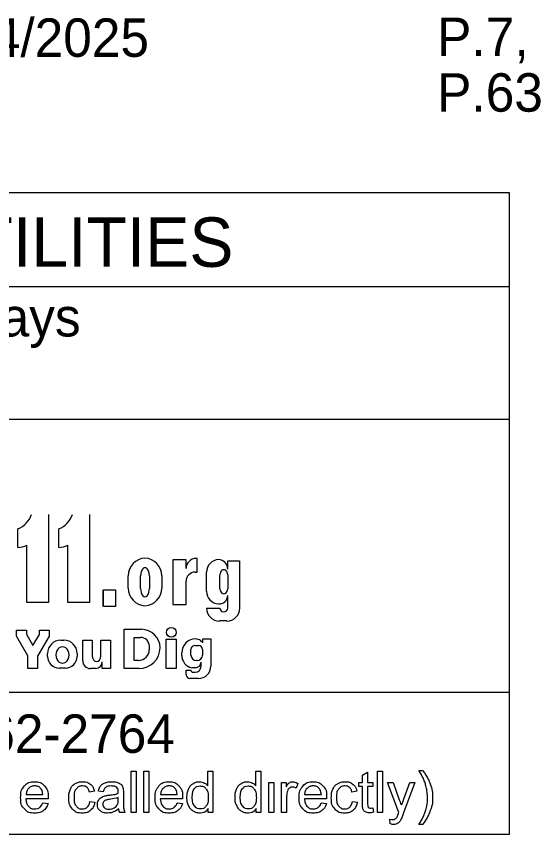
# Model space of a CAD drawing. Extents: x 0 to 34, y -32.5 to 22.
# Drawn here: x 4.831 to 6.74, y 2.305 to 5.285 of the extents above; entities that cross this region are included whole.
import ezdxf

# ---------------------------------------------------------------- set-up
doc = ezdxf.new("R2010")
doc.units = 0
doc.layers.add('GM_X_Adjacent_County', color=7, linetype='Continuous')
doc.layers.add('GM_X_Township', color=7, linetype='Continuous')

msp = doc.modelspace()

# ---------------------------------------------------------------- linework, layer by layer
at = {"layer": 'GM_X_Adjacent_County'}
for p, q in [((4.9487, 3.4706), (4.9487, 3.1506)), ((5.0975, 3.4706), (5.0975, 3.1506)), ((4.8371, 3.3499), (4.8371, 3.418)), ((4.9859, 3.3499), (4.9859, 3.418)), ((4.8694, 3.1506), (4.8694, 3.3592)), ((5.0182, 3.1506), (5.0182, 3.3592)), ((5.49, 3.3106), (5.486, 3.3106)), ((5.49, 3.2607), (5.49, 3.3106)), ((5.4493, 3.3054), (5.4005, 3.3054)), ((5.4005, 3.3054), (5.4005, 3.1425)), ((5.4493, 3.2739), (5.4493, 3.3054)), ((5.6009, 3.2713), (5.6009, 3.3023)), ((5.6009, 3.3023), (5.6444, 3.3023)), ((5.6444, 3.3023), (5.6444, 3.1294)), ((5.4823, 3.2607), (5.49, 3.2607)), ((5.5239, 3.1908), (5.5239, 3.2605)), ((5.5723, 3.2002), (5.5723, 3.2512)), ((5.6009, 3.2512), (5.6009, 3.2002)), ((5.2385, 3.2023), (5.2385, 3.2477)), ((5.2835, 3.2015), (5.2835, 3.2477)), ((5.3157, 3.2477), (5.3157, 3.2015)), ((5.3606, 3.2477), (5.3606, 3.2023)), ((5.4493, 3.1425), (5.4493, 3.2277)), ((5.1456, 3.1956), (5.1456, 3.1355)), ((5.6009, 3.1294), (5.6009, 3.1758)), ((4.9487, 3.1506), (4.8694, 3.1506)), ((5.0975, 3.1506), (5.0182, 3.1506)), ((5.4005, 3.1425), (5.4493, 3.1425)), ((5.5239, 3.1294), (5.5723, 3.1294)), ((5.5977, 3.0827), (5.5707, 3.0827)), ((4.8319, 3.0489), (4.8677, 3.0489)), ((4.8319, 3.0274), (4.8319, 3.0489)), ((4.8677, 3.0489), (4.8677, 3.0353)), ((4.9151, 3.0337), (4.9151, 3.0489)), ((4.9151, 3.0489), (4.9509, 3.0489)), ((4.9509, 3.0489), (4.9509, 3.0274)), ((5.2243, 3.0525), (5.2866, 3.0525)), ((5.2243, 2.9097), (5.2243, 3.0525)), ((4.8732, 2.9564), (4.8319, 3.0274)), ((4.8677, 3.0353), (4.8918, 2.9939)), ((4.8918, 2.9939), (4.9151, 3.0337)), ((4.9509, 3.0274), (4.9088, 2.955)), ((4.9925, 3.0126), (5.0047, 3.0126)), ((5.0727, 3.0126), (5.1075, 3.0126)), ((5.0727, 2.9381), (5.0727, 3.0126)), ((5.1075, 3.0126), (5.1075, 2.9573)), ((5.1388, 2.9556), (5.1388, 3.0126)), ((5.1388, 3.0126), (5.1736, 3.0126)), ((5.1736, 3.0126), (5.1736, 2.9097)), ((5.2603, 2.9391), (5.2603, 3.0232)), ((5.2603, 3.0232), (5.2828, 3.0232)), ((5.377, 3.0168), (5.4126, 3.0168)), ((5.377, 2.9097), (5.377, 3.0168)), ((5.4126, 3.0168), (5.4126, 2.9097)), ((5.5021, 3.0112), (5.5107, 3.0046)), ((5.5107, 3.0172), (5.5395, 3.0172)), ((5.5107, 3.0046), (5.5107, 3.0172)), ((5.5107, 3.0172), (5.5395, 3.0172)), ((5.5395, 3.0172), (5.5395, 2.9186)), ((5.3154, 2.9905), (5.3154, 2.9786)), ((5.4816, 2.9938), (5.4944, 2.9938)), ((4.8732, 2.9097), (4.8732, 2.9564)), ((4.9088, 2.955), (4.9088, 2.9097)), ((4.9447, 2.954), (4.9447, 2.9648)), ((5.0525, 2.9648), (5.0525, 2.954)), ((5.4335, 2.9572), (5.4335, 2.9673)), ((5.467, 2.958), (5.467, 2.9792)), ((5.509, 2.9792), (5.509, 2.958)), ((5.1439, 2.9097), (5.1439, 2.9338)), ((5.2759, 2.9391), (5.2603, 2.9391)), ((5.4897, 2.9387), (5.4863, 2.9387)), ((5.5039, 2.9176), (5.5039, 2.933)), ((4.9088, 2.9097), (4.8732, 2.9097)), ((5.0097, 2.9113), (4.9875, 2.9113)), ((5.1199, 2.9097), (5.1011, 2.9097)), ((5.1736, 2.9097), (5.1439, 2.9097)), ((5.2779, 2.9097), (5.2243, 2.9097)), ((5.4126, 2.9097), (5.377, 2.9097)), ((5.45, 2.8864), (5.45, 2.9034)), ((5.45, 2.9034), (5.467, 2.9034)), ((5.4835, 2.9125), (5.4698, 2.9125)), ((5.4738, 2.8964), (5.4827, 2.8964)), ((5.4942, 2.8733), (5.4631, 2.8733))]:
    msp.add_line(p, q, dxfattribs=at)
msp.add_lwpolyline([(5.148, 3.1956), (5.1921, 3.1956), (5.1921, 3.1355), (5.148, 3.1355)], close=True, dxfattribs=at)
for points in [[(5.2491, 2.3858), (5.2491, 2.536), (5.2675, 2.536), (5.2675, 2.3858), (5.2491, 2.3858)], [(5.2956, 2.3858), (5.2956, 2.536), (5.3141, 2.536), (5.3141, 2.3858), (5.2956, 2.3858)], [(5.5285, 2.4821), (5.5285, 2.536), (5.5469, 2.536), (5.5469, 2.3858), (5.5299, 2.3858)], [(5.7034, 2.4821), (5.7034, 2.536), (5.7218, 2.536), (5.7218, 2.3858), (5.7048, 2.3858)], [(6.1465, 2.3858), (6.1465, 2.536), (6.1649, 2.536), (6.1649, 2.3858), (6.1465, 2.3858)], [(6.2974, 2.5385), (6.3105, 2.5385)], [(6.092, 2.4177), (6.092, 2.4803), (6.0784, 2.4803), (6.0784, 2.4946), (6.092, 2.4946), (6.092, 2.5216), (6.1105, 2.5326), (6.1105, 2.4946), (6.1289, 2.4946), (6.1289, 2.4803), (6.1105, 2.4803), (6.1105, 2.4166)], [(5.7509, 2.3858), (5.7509, 2.4946), (5.7693, 2.4946), (5.7693, 2.3858), (5.7509, 2.3858)], [(5.7971, 2.3858), (5.7971, 2.4946), (5.8137, 2.4946), (5.8137, 2.4782)], [(5.8562, 2.4912), (5.8497, 2.4741)], [(6.2243, 2.3857), (6.183, 2.4946), (6.2029, 2.4946), (6.2255, 2.4318)], [(6.241, 2.4312), (6.2643, 2.4946), (6.2827, 2.4946), (6.2414, 2.3839)], [(4.8669, 2.4506), (4.9277, 2.4506)], [(5.1154, 2.4626), (5.0974, 2.4599)], [(5.1479, 2.4611), (5.1298, 2.4635)], [(5.2209, 2.456), (5.2209, 2.4314)], [(5.3565, 2.4506), (5.4173, 2.4506)], [(5.881, 2.4506), (5.9418, 2.4506)], [(6.0712, 2.4626), (6.0532, 2.4599)], [(4.947, 2.4355), (4.8659, 2.4355)], [(4.9275, 2.4209), (4.9465, 2.4185)], [(5.099, 2.4256), (5.1171, 2.4232)], [(5.2023, 2.4336), (5.2024, 2.4404)], [(5.4366, 2.4355), (5.3555, 2.4355)], [(5.4171, 2.4209), (5.4361, 2.4185)], [(5.8155, 2.4428), (5.8155, 2.3858), (5.7971, 2.3858)], [(5.9611, 2.4355), (5.88, 2.4355)], [(5.9416, 2.4209), (5.9606, 2.4185)], [(6.0548, 2.4256), (6.0729, 2.4232)], [(5.2267, 2.3858), (5.2075, 2.3858)], [(5.5299, 2.3858), (5.5299, 2.3995)], [(5.7048, 2.3858), (5.7048, 2.3995)], [(6.1289, 2.4022), (6.1315, 2.386)], [(6.1928, 2.344), (6.1907, 2.3614)], [(6.3105, 2.3416), (6.2974, 2.3416)]]:
    msp.add_lwpolyline(points, dxfattribs=at)
msp.add_circle((5.3952, 3.0411), 0.0177, dxfattribs=at)
for centre, radius, start, end in [((4.8031, 3.4997), 0.0885, 292.5572, 340.7355), ((4.952, 3.4997), 0.0885, 292.5572, 340.7355), ((4.8291, 3.438), 0.0885, 275.1733, 297.0931), ((4.9779, 3.438), 0.0885, 275.1733, 297.0931), ((5.3024, 3.2477), 0.064, 92.5886, 180), ((5.2967, 3.2477), 0.064, 0, 87.4114), ((5.486, 3.2739), 0.0367, 90, 180), ((5.5698, 3.2605), 0.0459, 92.6865, 180), ((5.5658, 3.2713), 0.0351, 0, 86.9262), ((5.4823, 3.2277), 0.033, 90, 180), ((5.3024, 3.2023), 0.064, 180, 267.4114), ((5.2967, 3.2023), 0.064, 272.5886, 0), ((5.5702, 3.1908), 0.0463, 180, 265.7132), ((5.5696, 3.1758), 0.0313, 264.7825, 0), ((5.5707, 3.1294), 0.0468, 180, 270), ((5.5977, 3.1294), 0.0468, 270, 0), ((5.2866, 2.9842), 0.0682, 0.9944, 90), ((4.9925, 2.9648), 0.0478, 90, 180), ((5.0047, 2.9648), 0.0478, 0, 90), ((5.2828, 2.9905), 0.0327, 0, 90), ((5.4834, 2.9673), 0.0499, 89.0934, 180), ((5.4848, 2.9889), 0.0283, 52.1415, 91.2046), ((5.2779, 2.9867), 0.0769, 270, 359.0635), ((5.4816, 2.9792), 0.0146, 90, 180), ((5.4944, 2.9792), 0.0146, 0, 90), ((4.9875, 2.954), 0.0428, 180, 270), ((5.0097, 2.954), 0.0428, 270, 0), ((5.2759, 2.9786), 0.0395, 270, 0), ((5.4791, 2.9572), 0.0457, 180, 258.2203), ((5.4863, 2.958), 0.0193, 180, 270), ((5.4897, 2.958), 0.0193, 270, 0), ((5.1011, 2.9381), 0.0284, 180, 270), ((5.1199, 2.9338), 0.024, 270, 0), ((5.4835, 2.9328), 0.0203, 270, 0), ((5.4738, 2.9032), 0.00682, 180, 270), ((5.4827, 2.9176), 0.0212, 270, 0), ((5.4942, 2.9186), 0.0453, 270, 0), ((5.4631, 2.8864), 0.0131, 180, 270)]:
    msp.add_arc(centre, radius, start, end, dxfattribs=at)
for centre, major_axis, ratio, start_param, end_param in [((5.2996, 3.2477), (0, 0.0291), 0.553236, 4.712389, 7.853982), ((5.5866, 3.2512), (0, 0.0184), 0.777179, 4.712389, 7.853982), ((5.2996, 3.2015), (0, 0.0308), 0.522014, 1.570796, 4.712389), ((5.5866, 3.2002), (0, 0.0184), 0.777179, 1.570796, 4.712389), ((5.5866, 3.1294), (0.0143, 0), 0.959012, 3.141593, 6.283185), ((4.9991, 2.9594), (0, 0.029), 0.832186, 4.712389, 7.853982), ((4.9991, 2.9594), (0, 0.0302), 0.797287, 1.570796, 4.712389), ((5.1231, 2.9581), (-0.0011, 0.0231), 0.679042, 1.570796, 4.575961)]:
    msp.add_ellipse(centre, major_axis=major_axis, ratio=ratio, start_param=start_param, end_param=end_param, dxfattribs=at)
for points, degree in [([(6.2974, 2.3416), (6.3279, 2.3908), (6.3279, 2.4401), (6.3279, 2.4593), (6.3235, 2.4783), (6.32, 2.4936), (6.3138, 2.5078), (6.3098, 2.517), (6.2974, 2.5385)], 3), ([(6.3105, 2.5385), (6.3298, 2.5128), (6.339, 2.4869), (6.3469, 2.4645), (6.3469, 2.4402), (6.3469, 2.4125), (6.3363, 2.3867), (6.3257, 2.3609), (6.3105, 2.3416)], 3), ([(4.9465, 2.4185), (4.942, 2.4018), (4.9298, 2.3926), (4.9177, 2.3834), (4.8987, 2.3834), (4.8749, 2.3834), (4.8609, 2.3981), (4.8469, 2.4128), (4.8469, 2.4393), (4.8469, 2.4667), (4.861, 2.4819), (4.8752, 2.497), (4.8977, 2.497), (4.9195, 2.497), (4.9333, 2.4822), (4.9471, 2.4673), (4.9471, 2.4404), (4.9471, 2.4388), (4.947, 2.4355)], 3), ([(4.9277, 2.4506), (4.9265, 2.4644), (4.9207, 2.4712), (4.9119, 2.4819), (4.8979, 2.4819), (4.8852, 2.4819), (4.8765, 2.4734), (4.8678, 2.4649), (4.8669, 2.4506)], 3), ([(5.1171, 2.4232), (5.1141, 2.4045), (5.1019, 2.394), (5.0896, 2.3834), (5.0718, 2.3834), (5.0495, 2.3834), (5.0359, 2.398), (5.0223, 2.4126), (5.0223, 2.4398), (5.0223, 2.4574), (5.0282, 2.4706), (5.034, 2.4838), (5.046, 2.4904), (5.0579, 2.497), (5.0719, 2.497), (5.0897, 2.497), (5.1009, 2.4881), (5.1122, 2.4791), (5.1154, 2.4626)], 3), ([(5.0974, 2.4599), (5.0949, 2.4708), (5.0884, 2.4764), (5.0819, 2.4819), (5.0726, 2.4819), (5.0587, 2.4819), (5.05, 2.4719), (5.0413, 2.462), (5.0413, 2.4403), (5.0413, 2.4184), (5.0497, 2.4085), (5.0581, 2.3985), (5.0717, 2.3985), (5.0825, 2.3985), (5.0898, 2.4052), (5.0971, 2.4118), (5.099, 2.4256)], 3), ([(5.2038, 2.3992), (5.1936, 2.3905), (5.1841, 2.387), (5.1746, 2.3834), (5.1638, 2.3834), (5.1458, 2.3834), (5.1362, 2.3922), (5.1266, 2.4009), (5.1266, 2.4145), (5.1266, 2.4225), (5.1302, 2.4291), (5.1339, 2.4357), (5.1398, 2.4397), (5.1456, 2.4437), (5.153, 2.4457), (5.1584, 2.4471), (5.1694, 2.4485), (5.1917, 2.4511), (5.2023, 2.4548), (5.2024, 2.4586), (5.2024, 2.4596), (5.2024, 2.4709), (5.1971, 2.4756), (5.1901, 2.4818), (5.1762, 2.4818), (5.1632, 2.4818), (5.157, 2.4773), (5.1508, 2.4727), (5.1479, 2.4611)], 3), ([(5.1298, 2.4635), (5.1323, 2.4751), (5.1379, 2.4822), (5.1435, 2.4894), (5.1542, 2.4932), (5.1648, 2.497), (5.1788, 2.497), (5.1928, 2.497), (5.2015, 2.4938), (5.2102, 2.4905), (5.2142, 2.4855), (5.2183, 2.4805), (5.22, 2.473), (5.2209, 2.4682), (5.2209, 2.456)], 3), ([(5.4361, 2.4185), (5.4316, 2.4018), (5.4194, 2.3926), (5.4072, 2.3834), (5.3883, 2.3834), (5.3644, 2.3834), (5.3505, 2.3981), (5.3365, 2.4128), (5.3365, 2.4393), (5.3365, 2.4667), (5.3506, 2.4819), (5.3648, 2.497), (5.3873, 2.497), (5.4091, 2.497), (5.4229, 2.4822), (5.4367, 2.4673), (5.4367, 2.4404), (5.4367, 2.4388), (5.4366, 2.4355)], 3), ([(5.4173, 2.4506), (5.4161, 2.4644), (5.4103, 2.4712), (5.4015, 2.4819), (5.3875, 2.4819), (5.3748, 2.4819), (5.3661, 2.4734), (5.3574, 2.4649), (5.3565, 2.4506)], 3), ([(5.5299, 2.3995), (5.5195, 2.3834), (5.4995, 2.3834), (5.4865, 2.3834), (5.4755, 2.3906), (5.4646, 2.3977), (5.4586, 2.4106), (5.4526, 2.4234), (5.4526, 2.4401), (5.4526, 2.4564), (5.4581, 2.4697), (5.4635, 2.4829), (5.4743, 2.49), (5.4852, 2.497), (5.4986, 2.497), (5.5084, 2.497), (5.516, 2.4929), (5.5237, 2.4888), (5.5285, 2.4821)], 3), ([(5.4716, 2.4401), (5.4716, 2.4192), (5.4805, 2.4089), (5.4893, 2.3985), (5.5012, 2.3985), (5.5133, 2.3985), (5.5218, 2.4084), (5.5302, 2.4183), (5.5302, 2.4386), (5.5302, 2.4609), (5.5216, 2.4714), (5.513, 2.4818), (5.5004, 2.4818), (5.4881, 2.4818), (5.4799, 2.4718), (5.4716, 2.4617), (5.4716, 2.4401)], 3), ([(5.7048, 2.3995), (5.6944, 2.3834), (5.6743, 2.3834), (5.6613, 2.3834), (5.6504, 2.3906), (5.6395, 2.3977), (5.6335, 2.4106), (5.6275, 2.4234), (5.6275, 2.4401), (5.6275, 2.4564), (5.6329, 2.4697), (5.6384, 2.4829), (5.6492, 2.49), (5.66, 2.497), (5.6734, 2.497), (5.6832, 2.497), (5.6909, 2.4929), (5.6986, 2.4888), (5.7034, 2.4821)], 3), ([(5.6465, 2.4401), (5.6465, 2.4192), (5.6553, 2.4089), (5.6641, 2.3985), (5.6761, 2.3985), (5.6882, 2.3985), (5.6967, 2.4084), (5.7051, 2.4183), (5.7051, 2.4386), (5.7051, 2.4609), (5.6965, 2.4714), (5.6879, 2.4818), (5.6753, 2.4818), (5.663, 2.4818), (5.6548, 2.4718), (5.6465, 2.4617), (5.6465, 2.4401)], 3), ([(5.8137, 2.4782), (5.8201, 2.4897), (5.8254, 2.4934), (5.8308, 2.497), (5.8372, 2.497), (5.8466, 2.497), (5.8562, 2.4912)], 3), ([(5.8497, 2.4741), (5.843, 2.478), (5.8363, 2.478), (5.8302, 2.478), (5.8255, 2.4744), (5.8207, 2.4708), (5.8186, 2.4643), (5.8155, 2.4545), (5.8155, 2.4428)], 3), ([(5.9606, 2.4185), (5.9561, 2.4018), (5.9439, 2.3926), (5.9317, 2.3834), (5.9128, 2.3834), (5.8889, 2.3834), (5.875, 2.3981), (5.861, 2.4128), (5.861, 2.4393), (5.861, 2.4667), (5.8751, 2.4819), (5.8892, 2.497), (5.9118, 2.497), (5.9336, 2.497), (5.9474, 2.4822), (5.9612, 2.4673), (5.9612, 2.4404), (5.9612, 2.4388), (5.9611, 2.4355)], 3), ([(5.9418, 2.4506), (5.9405, 2.4644), (5.9348, 2.4712), (5.926, 2.4819), (5.912, 2.4819), (5.8993, 2.4819), (5.8906, 2.4734), (5.8819, 2.4649), (5.881, 2.4506)], 3), ([(6.0729, 2.4232), (6.07, 2.4045), (6.0577, 2.394), (6.0455, 2.3834), (6.0277, 2.3834), (6.0053, 2.3834), (5.9917, 2.398), (5.9782, 2.4126), (5.9782, 2.4398), (5.9782, 2.4574), (5.984, 2.4706), (5.9899, 2.4838), (6.0018, 2.4904), (6.0137, 2.497), (6.0278, 2.497), (6.0455, 2.497), (6.0568, 2.4881), (6.068, 2.4791), (6.0712, 2.4626)], 3), ([(6.0532, 2.4599), (6.0507, 2.4708), (6.0442, 2.4764), (6.0377, 2.4819), (6.0285, 2.4819), (6.0146, 2.4819), (6.0059, 2.4719), (5.9972, 2.462), (5.9972, 2.4403), (5.9972, 2.4184), (6.0056, 2.4085), (6.014, 2.3985), (6.0275, 2.3985), (6.0384, 2.3985), (6.0456, 2.4052), (6.0529, 2.4118), (6.0548, 2.4256)], 3), ([(4.8659, 2.4355), (4.8669, 2.4176), (4.876, 2.408), (4.8852, 2.3985), (4.8988, 2.3985), (4.9089, 2.3985), (4.9161, 2.4039), (4.9233, 2.4092), (4.9275, 2.4209)], 3), ([(5.2024, 2.4404), (5.1923, 2.4363), (5.1722, 2.4334), (5.1608, 2.4318), (5.1561, 2.4298), (5.1514, 2.4277), (5.1488, 2.4238), (5.1463, 2.4198), (5.1463, 2.415), (5.1463, 2.4076), (5.1519, 2.4027), (5.1574, 2.3978), (5.1682, 2.3978), (5.1788, 2.3978), (5.1871, 2.4025), (5.1954, 2.4071), (5.1993, 2.4152), (5.2023, 2.4215), (5.2023, 2.4336)], 3), ([(5.2209, 2.4314), (5.2209, 2.4057), (5.2221, 2.3989), (5.2233, 2.3921), (5.2267, 2.3858)], 3), ([(5.3555, 2.4355), (5.3565, 2.4176), (5.3656, 2.408), (5.3748, 2.3985), (5.3884, 2.3985), (5.3985, 2.3985), (5.4057, 2.4039), (5.4129, 2.4092), (5.4171, 2.4209)], 3), ([(5.88, 2.4355), (5.881, 2.4176), (5.8901, 2.408), (5.8992, 2.3985), (5.9129, 2.3985), (5.923, 2.3985), (5.9302, 2.4039), (5.9374, 2.4092), (5.9416, 2.4209)], 3), ([(6.1315, 2.386), (6.1238, 2.3843), (6.1176, 2.3843), (6.1076, 2.3843), (6.1021, 2.3875), (6.0965, 2.3907), (6.0943, 2.3959), (6.092, 2.401), (6.092, 2.4177)], 3), ([(6.1105, 2.4166), (6.1105, 2.4087), (6.1114, 2.4064), (6.1124, 2.4042), (6.1146, 2.4028), (6.1168, 2.4015), (6.1209, 2.4015), (6.1239, 2.4015), (6.1289, 2.4022)], 3), ([(6.2255, 2.4318), (6.2299, 2.4199), (6.2334, 2.4067), (6.2366, 2.4191), (6.241, 2.4312)], 3), ([(5.2075, 2.3858), (5.2047, 2.3915), (5.2038, 2.3992)], 2), ([(6.1907, 2.3614), (6.1967, 2.3597), (6.2012, 2.3597), (6.2074, 2.3597), (6.211, 2.3618), (6.2147, 2.3638), (6.2171, 2.3675), (6.2188, 2.3703), (6.2227, 2.3812), (6.2232, 2.3827), (6.2243, 2.3857)], 3), ([(6.2414, 2.3839), (6.2348, 2.366), (6.2311, 2.3593), (6.2262, 2.3502), (6.2198, 2.346), (6.2135, 2.3417), (6.2046, 2.3417), (6.1993, 2.3417), (6.1928, 2.344)], 3)]:
    msp.add_open_spline(points, degree=degree, dxfattribs=at)
at = {"layer": 'GM_X_Township'}
for p, q in [((6.6275, 4.6422), (2.3775, 4.6422)), ((6.6275, 2.3047), (6.6275, 4.6422)), ((2.3775, 4.3006), (6.6275, 4.3006)), ((2.3775, 3.8172), (6.6275, 3.8172)), ((6.6275, 2.8225), (2.3775, 2.8225)), ((6.6275, 2.3047), (2.3775, 2.3047))]:
    msp.add_line(p, q, dxfattribs=at)

# ---------------------------------------------------------------- texts
at = {"layer": 'GM_X_Adjacent_County'}
for s, height, p in [('3/14/2025', 0.14, (4.4815, 5.1372)), ('P.7', 0.14, (6.3635, 5.14)), (', ', 0.14, (6.6449, 5.14)), ('P.63', 0.14, (6.3635, 4.9375)), ('UNDERGROUND UTILITIES', 0.18, (2.5057, 4.3725)), ('Contact Two Working Days', 0.14, (2.7972, 4.119)), ('OHIO811, 8-1-1, or 1-800-362-2764', 0.14, (2.422, 2.6025))]:
    msp.add_text(s, height=height, dxfattribs=at).set_placement(p)

doc.saveas('drawing.dxf')
